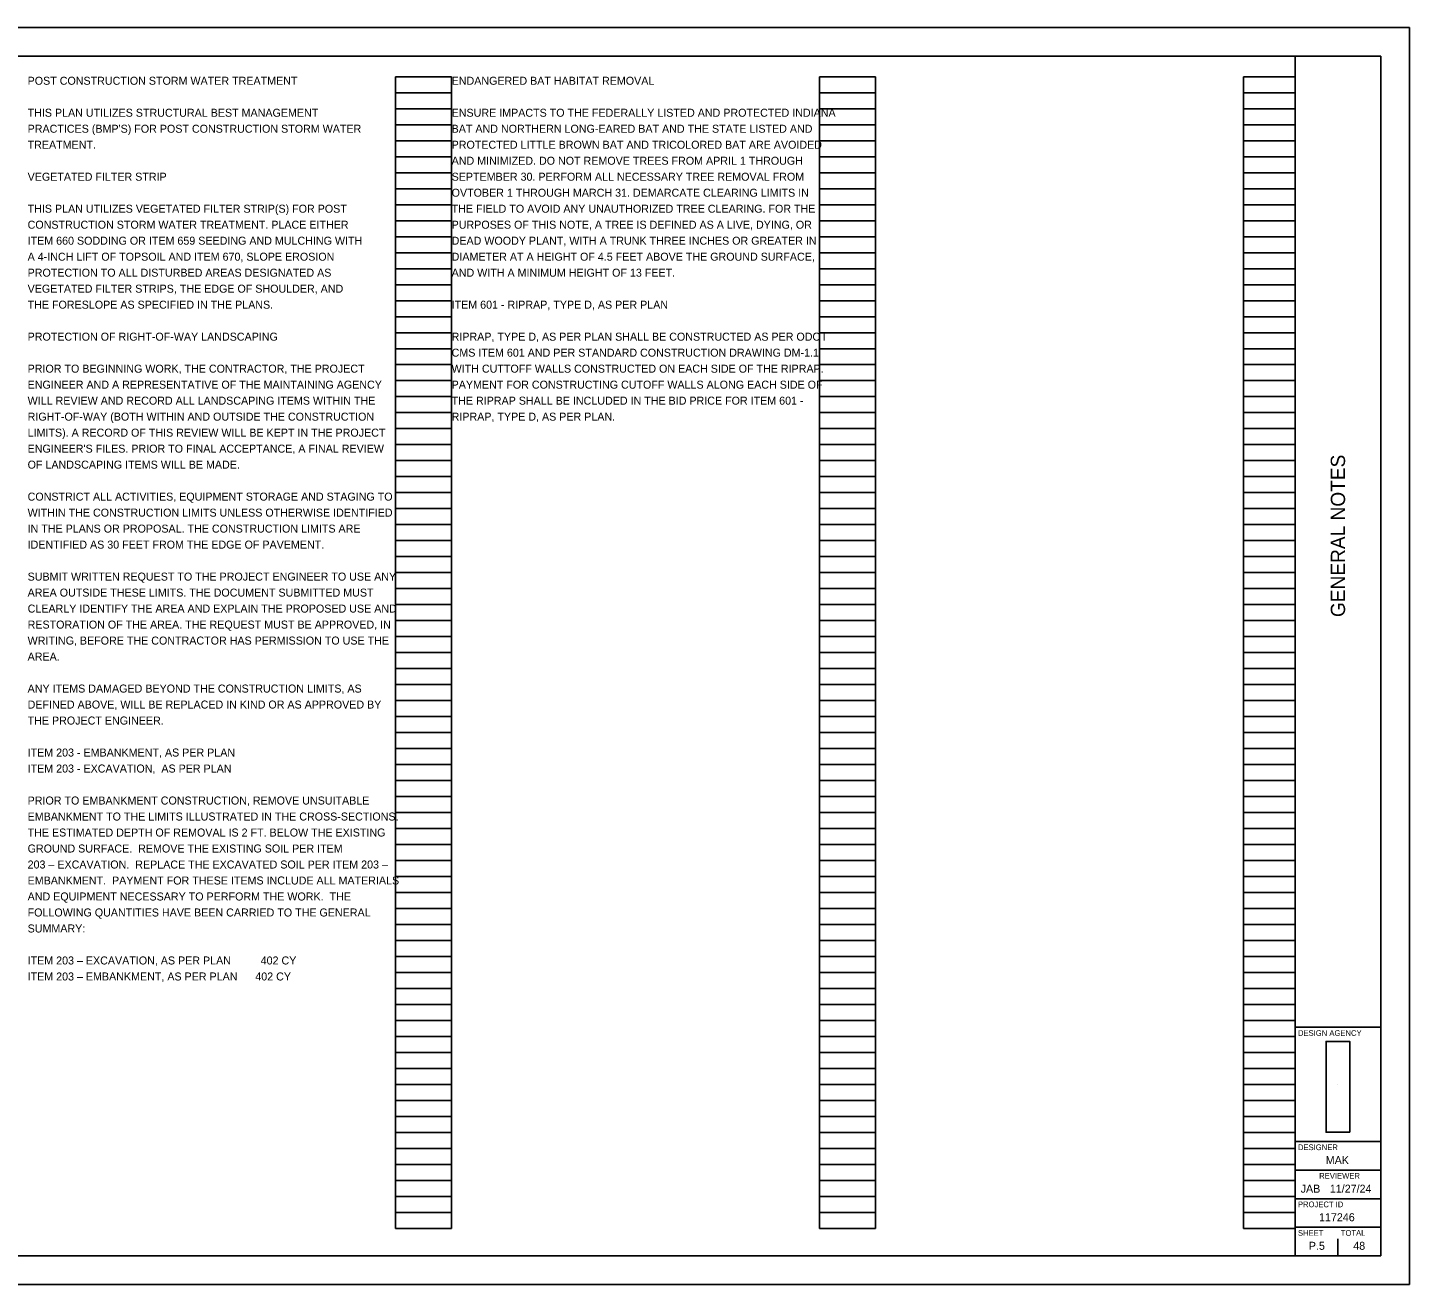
# Model space of a CAD drawing. Extents: x -14.4 to 34, y 0 to 22.
# Drawn here: x 9.82 to 34, y 0 to 22 of the extents above; entities that cross this region are included whole.
import ezdxf

# ---------------------------------------------------------------- set-up
doc = ezdxf.new("R2010")
doc.units = 0
for name, color, linetype in [('SH_Border', 7, 'Continuous'), ('SH_Cut_Line', 7, 'Continuous'), ('SH_Data', 7, 'Continuous'), ('SH_Text', 7, 'Continuous')]:
    doc.layers.add(name, color=color, linetype=linetype)

msp = doc.modelspace()

# ---------------------------------------------------------------- linework, layer by layer
at = {"layer": 'SH_Border'}
for p, q in [((32, 0.5), (32, 21.5)), ((32, 4.5), (33.5, 4.5)), ((32, 2.5), (33.5, 2.5)), ((32, 2), (33.5, 2)), ((32, 1.5), (33.5, 1.5)), ((32, 1), (33.5, 1))]:
    msp.add_line(p, q, dxfattribs=at)
msp.add_lwpolyline([(1.5, 21.5), (33.5, 21.5), (33.5, 0.5), (1.5, 0.5)], close=True, dxfattribs=at)
at = {"layer": 'SH_Cut_Line'}
msp.add_lwpolyline([(0, 0), (34, 0), (34, 22), (0, 22)], close=True, dxfattribs=at)
at = {"layer": 'SH_Data'}
for p, q in [((16.26, 0.98), (16.26, 21.14)), ((16.26, 21.14), (17.24, 21.14)), ((17.24, 0.98), (17.24, 21.14)), ((23.68, 0.98), (23.68, 21.14)), ((23.68, 21.14), (24.66, 21.14)), ((24.66, 0.98), (24.66, 21.14)), ((31.1, 0.98), (31.1, 21.14)), ((31.1, 21.14), (32, 21.14)), ((32, 0.98), (32, 21.14)), ((16.26, 20.86), (17.24, 20.86)), ((23.68, 20.86), (24.66, 20.86)), ((31.1, 20.86), (32, 20.86)), ((16.26, 20.58), (17.24, 20.58)), ((23.68, 20.58), (24.66, 20.58)), ((31.1, 20.58), (32, 20.58)), ((16.26, 20.3), (17.24, 20.3)), ((23.68, 20.3), (24.66, 20.3)), ((31.1, 20.3), (32, 20.3)), ((16.26, 20.02), (17.24, 20.02)), ((23.68, 20.02), (24.66, 20.02)), ((31.1, 20.02), (32, 20.02)), ((16.26, 19.74), (17.24, 19.74)), ((23.68, 19.74), (24.66, 19.74)), ((31.1, 19.74), (32, 19.74)), ((16.26, 19.46), (17.24, 19.46)), ((23.68, 19.46), (24.66, 19.46)), ((31.1, 19.46), (32, 19.46)), ((16.26, 19.18), (17.24, 19.18)), ((23.68, 19.18), (24.66, 19.18)), ((31.1, 19.18), (32, 19.18)), ((16.26, 18.9), (17.24, 18.9)), ((23.68, 18.9), (24.66, 18.9)), ((31.1, 18.9), (32, 18.9)), ((16.26, 18.62), (17.24, 18.62)), ((23.68, 18.62), (24.66, 18.62)), ((31.1, 18.62), (32, 18.62)), ((16.26, 18.34), (17.24, 18.34)), ((23.68, 18.34), (24.66, 18.34)), ((31.1, 18.34), (32, 18.34)), ((16.26, 18.06), (17.24, 18.06)), ((23.68, 18.06), (24.66, 18.06)), ((31.1, 18.06), (32, 18.06)), ((16.26, 17.78), (17.24, 17.78)), ((23.68, 17.78), (24.66, 17.78)), ((31.1, 17.78), (32, 17.78)), ((16.26, 17.5), (17.24, 17.5)), ((23.68, 17.5), (24.66, 17.5)), ((31.1, 17.5), (32, 17.5)), ((16.26, 17.22), (17.24, 17.22)), ((23.68, 17.22), (24.66, 17.22)), ((31.1, 17.22), (32, 17.22)), ((16.26, 16.94), (17.24, 16.94)), ((23.68, 16.94), (24.66, 16.94)), ((31.1, 16.94), (32, 16.94)), ((16.26, 16.66), (17.24, 16.66)), ((23.68, 16.66), (24.66, 16.66)), ((31.1, 16.66), (32, 16.66)), ((16.26, 16.38), (17.24, 16.38)), ((23.68, 16.38), (24.66, 16.38)), ((31.1, 16.38), (32, 16.38)), ((16.26, 16.1), (17.24, 16.1)), ((23.68, 16.1), (24.66, 16.1)), ((31.1, 16.1), (32, 16.1)), ((16.26, 15.82), (17.24, 15.82)), ((23.68, 15.82), (24.66, 15.82)), ((31.1, 15.82), (32, 15.82)), ((16.26, 15.54), (17.24, 15.54)), ((23.68, 15.54), (24.66, 15.54)), ((31.1, 15.54), (32, 15.54)), ((16.26, 15.26), (17.24, 15.26)), ((23.68, 15.26), (24.66, 15.26)), ((31.1, 15.26), (32, 15.26)), ((16.26, 14.98), (17.24, 14.98)), ((23.68, 14.98), (24.66, 14.98)), ((31.1, 14.98), (32, 14.98)), ((16.26, 14.7), (17.24, 14.7)), ((23.68, 14.7), (24.66, 14.7)), ((31.1, 14.7), (32, 14.7)), ((16.26, 14.42), (17.24, 14.42)), ((23.68, 14.42), (24.66, 14.42)), ((31.1, 14.42), (32, 14.42)), ((16.26, 14.14), (17.24, 14.14)), ((23.68, 14.14), (24.66, 14.14)), ((31.1, 14.14), (32, 14.14)), ((16.26, 13.86), (17.24, 13.86)), ((23.68, 13.86), (24.66, 13.86)), ((31.1, 13.86), (32, 13.86)), ((16.26, 13.58), (17.24, 13.58)), ((23.68, 13.58), (24.66, 13.58)), ((31.1, 13.58), (32, 13.58)), ((16.26, 13.3), (17.24, 13.3)), ((23.68, 13.3), (24.66, 13.3)), ((31.1, 13.3), (32, 13.3)), ((16.26, 13.02), (17.24, 13.02)), ((23.68, 13.02), (24.66, 13.02)), ((31.1, 13.02), (32, 13.02)), ((16.26, 12.74), (17.24, 12.74)), ((23.68, 12.74), (24.66, 12.74)), ((31.1, 12.74), (32, 12.74)), ((16.26, 12.46), (17.24, 12.46)), ((23.68, 12.46), (24.66, 12.46)), ((31.1, 12.46), (32, 12.46)), ((16.26, 12.18), (17.24, 12.18)), ((23.68, 12.18), (24.66, 12.18)), ((31.1, 12.18), (32, 12.18)), ((16.26, 11.9), (17.24, 11.9)), ((23.68, 11.9), (24.66, 11.9)), ((31.1, 11.9), (32, 11.9)), ((16.26, 11.62), (17.24, 11.62)), ((23.68, 11.62), (24.66, 11.62)), ((31.1, 11.62), (32, 11.62)), ((16.26, 11.34), (17.24, 11.34)), ((23.68, 11.34), (24.66, 11.34)), ((31.1, 11.34), (32, 11.34)), ((16.26, 11.06), (17.24, 11.06)), ((23.68, 11.06), (24.66, 11.06)), ((31.1, 11.06), (32, 11.06)), ((16.26, 10.78), (17.24, 10.78)), ((23.68, 10.78), (24.66, 10.78)), ((31.1, 10.78), (32, 10.78)), ((16.26, 10.5), (17.24, 10.5)), ((23.68, 10.5), (24.66, 10.5)), ((31.1, 10.5), (32, 10.5)), ((16.26, 10.22), (17.24, 10.22)), ((23.68, 10.22), (24.66, 10.22)), ((31.1, 10.22), (32, 10.22)), ((16.26, 9.94), (17.24, 9.94)), ((23.68, 9.94), (24.66, 9.94)), ((31.1, 9.94), (32, 9.94)), ((16.26, 9.66), (17.24, 9.66)), ((23.68, 9.66), (24.66, 9.66)), ((31.1, 9.66), (32, 9.66)), ((16.26, 9.38), (17.24, 9.38)), ((23.68, 9.38), (24.66, 9.38)), ((31.1, 9.38), (32, 9.38)), ((16.26, 9.1), (17.24, 9.1)), ((23.68, 9.1), (24.66, 9.1)), ((31.1, 9.1), (32, 9.1)), ((16.26, 8.82), (17.24, 8.82)), ((23.68, 8.82), (24.66, 8.82)), ((31.1, 8.82), (32, 8.82)), ((16.26, 8.54), (17.24, 8.54)), ((23.68, 8.54), (24.66, 8.54)), ((31.1, 8.54), (32, 8.54)), ((16.26, 8.26), (17.24, 8.26)), ((23.68, 8.26), (24.66, 8.26)), ((31.1, 8.26), (32, 8.26)), ((16.26, 7.98), (17.24, 7.98)), ((23.68, 7.98), (24.66, 7.98)), ((31.1, 7.98), (32, 7.98)), ((16.26, 7.7), (17.24, 7.7)), ((23.68, 7.7), (24.66, 7.7)), ((31.1, 7.7), (32, 7.7)), ((16.26, 7.42), (17.24, 7.42)), ((23.68, 7.42), (24.66, 7.42)), ((31.1, 7.42), (32, 7.42)), ((16.26, 7.14), (17.24, 7.14)), ((23.68, 7.14), (24.66, 7.14)), ((31.1, 7.14), (32, 7.14)), ((16.26, 6.86), (17.24, 6.86)), ((23.68, 6.86), (24.66, 6.86)), ((31.1, 6.86), (32, 6.86)), ((16.26, 6.58), (17.24, 6.58)), ((23.68, 6.58), (24.66, 6.58)), ((31.1, 6.58), (32, 6.58)), ((16.26, 6.3), (17.24, 6.3)), ((23.68, 6.3), (24.66, 6.3)), ((31.1, 6.3), (32, 6.3)), ((16.26, 6.02), (17.24, 6.02)), ((23.68, 6.02), (24.66, 6.02)), ((31.1, 6.02), (32, 6.02)), ((16.26, 5.74), (17.24, 5.74)), ((23.68, 5.74), (24.66, 5.74)), ((31.1, 5.74), (32, 5.74)), ((16.26, 5.46), (17.24, 5.46)), ((23.68, 5.46), (24.66, 5.46)), ((31.1, 5.46), (32, 5.46)), ((16.26, 5.18), (17.24, 5.18)), ((23.68, 5.18), (24.66, 5.18)), ((31.1, 5.18), (32, 5.18)), ((16.26, 4.9), (17.24, 4.9)), ((23.68, 4.9), (24.66, 4.9)), ((31.1, 4.9), (32, 4.9)), ((16.26, 4.62), (17.24, 4.62)), ((23.68, 4.62), (24.66, 4.62)), ((31.1, 4.62), (32, 4.62)), ((16.26, 4.34), (17.24, 4.34)), ((23.68, 4.34), (24.66, 4.34)), ((31.1, 4.34), (32, 4.34)), ((16.26, 4.06), (17.24, 4.06)), ((23.68, 4.06), (24.66, 4.06)), ((31.1, 4.06), (32, 4.06)), ((16.26, 3.78), (17.24, 3.78)), ((23.68, 3.78), (24.66, 3.78)), ((31.1, 3.78), (32, 3.78)), ((16.26, 3.5), (17.24, 3.5)), ((23.68, 3.5), (24.66, 3.5)), ((31.1, 3.5), (32, 3.5)), ((32.75, 3.5), (32.75, 3.5)), ((16.26, 3.22), (17.24, 3.22)), ((23.68, 3.22), (24.66, 3.22)), ((31.1, 3.22), (32, 3.22)), ((16.26, 2.94), (17.24, 2.94)), ((23.68, 2.94), (24.66, 2.94)), ((31.1, 2.94), (32, 2.94)), ((16.26, 2.66), (17.24, 2.66)), ((23.68, 2.66), (24.66, 2.66)), ((31.1, 2.66), (32, 2.66)), ((16.26, 2.38), (17.24, 2.38)), ((23.68, 2.38), (24.66, 2.38)), ((31.1, 2.38), (32, 2.38)), ((16.26, 2.1), (17.24, 2.1)), ((23.68, 2.1), (24.66, 2.1)), ((31.1, 2.1), (32, 2.1)), ((16.26, 1.82), (17.24, 1.82)), ((23.68, 1.82), (24.66, 1.82)), ((31.1, 1.82), (32, 1.82)), ((16.26, 1.54), (17.24, 1.54)), ((23.68, 1.54), (24.66, 1.54)), ((31.1, 1.54), (32, 1.54)), ((16.26, 1.26), (17.24, 1.26)), ((23.68, 1.26), (24.66, 1.26)), ((31.1, 1.26), (32, 1.26)), ((16.26, 0.98), (17.24, 0.98)), ((23.68, 0.98), (24.66, 0.98)), ((31.1, 0.98), (32, 0.98)), ((32.75, 0.5), (32.75, 0.8)), ((32.375, 0.675), (32.375, 0.675))]:
    msp.add_line(p, q, dxfattribs=at)
at = {"layer": 'SH_Text'}
msp.add_lwpolyline([(32.956, 2.664), (32.956, 4.254), (32.544, 4.254), (32.544, 2.664)], close=True, dxfattribs=at)

# ---------------------------------------------------------------- texts
at = {"layer": 'SH_Data'}
msp.add_text('GENERAL NOTES', height=0.25, rotation=90, dxfattribs=at).set_placement((32.875, 11.682))
for s, height, p in [('DESIGN AGENCY', 0.1, (32.05, 4.35)), ('DESIGNER', 0.1, (32.05, 2.35)), ('MAK', 0.14, (32.537, 2.105)), ('REVIEWER', 0.1, (32.422, 1.85)), ('JAB', 0.14, (32.098, 1.605)), ('11/27/24', 0.14, (32.608, 1.605)), ('PROJECT ID', 0.1, (32.05, 1.35)), ('117246', 0.14, (32.419, 1.105)), ('SHEET', 0.1, (32.05, 0.85)), ('P.5', 0.14, (32.241, 0.605)), ('TOTAL', 0.1, (32.8, 0.85)), ('48', 0.14, (33.018, 0.605))]:
    msp.add_text(s, height=height, dxfattribs=at).set_placement(p)
at = {"layer": 'SH_Text'}
for s, p in [('POST CONSTRUCTION STORM WATER TREATMENT', (9.82, 21)), ('ENDANGERED BAT HABITAT REMOVAL', (17.24, 21)), ('THIS PLAN UTILIZES STRUCTURAL BEST MANAGEMENT', (9.82, 20.44)), ('ENSURE IMPACTS TO THE FEDERALLY LISTED AND PROTECTED INDIANA ', (17.24, 20.44)), ("PRACTICES (BMP'S) FOR POST CONSTRUCTION STORM WATER", (9.82, 20.16)), ('BAT AND NORTHERN LONG-EARED BAT AND THE STATE LISTED AND ', (17.24, 20.16)), ('TREATMENT.', (9.82, 19.88)), ('PROTECTED LITTLE BROWN BAT AND TRICOLORED BAT ARE AVOIDED ', (17.24, 19.88)), ('AND MINIMIZED. DO NOT REMOVE TREES FROM APRIL 1 THROUGH ', (17.24, 19.6)), ('VEGETATED FILTER STRIP', (9.82, 19.32)), ('SEPTEMBER 30. PERFORM ALL NECESSARY TREE REMOVAL FROM ', (17.24, 19.32)), ('OVTOBER 1 THROUGH MARCH 31. DEMARCATE CLEARING LIMITS IN ', (17.24, 19.04)), ('THIS PLAN UTILIZES VEGETATED FILTER STRIP(S) FOR POST', (9.82, 18.76)), ('THE FIELD TO AVOID ANY UNAUTHORIZED TREE CLEARING. FOR THE ', (17.24, 18.76)), ('CONSTRUCTION STORM WATER TREATMENT. PLACE EITHER', (9.82, 18.48)), ('PURPOSES OF THIS NOTE, A TREE IS DEFINED AS A LIVE, DYING, OR ', (17.24, 18.48)), ('ITEM 660 SODDING OR ITEM 659 SEEDING AND MULCHING WITH', (9.82, 18.2)), ('DEAD WOODY PLANT, WITH A TRUNK THREE INCHES OR GREATER IN ', (17.24, 18.2)), ('A 4-INCH LIFT OF TOPSOIL AND ITEM 670, SLOPE EROSION', (9.82, 17.92)), ('DIAMETER AT A HEIGHT OF 4.5 FEET ABOVE THE GROUND SURFACE, ', (17.24, 17.92)), ('PROTECTION TO ALL DISTURBED AREAS DESIGNATED AS', (9.82, 17.64)), ('AND WITH A MINIMUM HEIGHT OF 13 FEET.', (17.24, 17.64)), ('VEGETATED FILTER STRIPS, THE EDGE OF SHOULDER, AND', (9.82, 17.36)), ('THE FORESLOPE AS SPECIFIED IN THE PLANS.', (9.82, 17.08)), ('ITEM 601 - RIPRAP, TYPE D, AS PER PLAN', (17.24, 17.08)), ('PROTECTION OF RIGHT-OF-WAY LANDSCAPING', (9.82, 16.52)), ('RIPRAP, TYPE D, AS PER PLAN SHALL BE CONSTRUCTED AS PER ODOT ', (17.24, 16.52)), ('CMS ITEM 601 AND PER STANDARD CONSTRUCTION DRAWING DM-1.1 ', (17.24, 16.24)), ('PRIOR TO BEGINNING WORK, THE CONTRACTOR, THE PROJECT', (9.82, 15.96)), ('WITH CUTTOFF WALLS CONSTRUCTED ON EACH SIDE OF THE RIPRAP. ', (17.24, 15.96)), ('ENGINEER AND A REPRESENTATIVE OF THE MAINTAINING AGENCY', (9.82, 15.68)), ('PAYMENT FOR CONSTRUCTING CUTOFF WALLS ALONG EACH SIDE OF ', (17.24, 15.68)), ('WILL REVIEW AND RECORD ALL LANDSCAPING ITEMS WITHIN THE', (9.82, 15.4)), ('THE RIPRAP SHALL BE INCLUDED IN THE BID PRICE FOR ITEM 601 - ', (17.24, 15.4)), ('RIGHT-OF-WAY (BOTH WITHIN AND OUTSIDE THE CONSTRUCTION', (9.82, 15.12)), ('RIPRAP, TYPE D, AS PER PLAN.', (17.24, 15.12)), ('LIMITS). A RECORD OF THIS REVIEW WILL BE KEPT IN THE PROJECT', (9.82, 14.84)), ("ENGINEER'S FILES. PRIOR TO FINAL ACCEPTANCE, A FINAL REVIEW", (9.82, 14.56)), ('OF LANDSCAPING ITEMS WILL BE MADE.', (9.82, 14.28)), ('CONSTRICT ALL ACTIVITIES, EQUIPMENT STORAGE AND STAGING TO', (9.82, 13.72)), ('WITHIN THE CONSTRUCTION LIMITS UNLESS OTHERWISE IDENTIFIED', (9.82, 13.44)), ('IN THE PLANS OR PROPOSAL. THE CONSTRUCTION LIMITS ARE', (9.82, 13.16)), ('IDENTIFIED AS 30 FEET FROM THE EDGE OF PAVEMENT.', (9.82, 12.88)), ('SUBMIT WRITTEN REQUEST TO THE PROJECT ENGINEER TO USE ANY', (9.82, 12.32)), ('AREA OUTSIDE THESE LIMITS. THE DOCUMENT SUBMITTED MUST', (9.82, 12.04)), ('CLEARLY IDENTIFY THE AREA AND EXPLAIN THE PROPOSED USE AND', (9.82, 11.76)), ('RESTORATION OF THE AREA. THE REQUEST MUST BE APPROVED, IN', (9.82, 11.48)), ('WRITING, BEFORE THE CONTRACTOR HAS PERMISSION TO USE THE', (9.82, 11.2)), ('AREA.', (9.82, 10.92)), ('ANY ITEMS DAMAGED BEYOND THE CONSTRUCTION LIMITS, AS', (9.82, 10.36)), ('DEFINED ABOVE, WILL BE REPLACED IN KIND OR AS APPROVED BY', (9.82, 10.08)), ('THE PROJECT ENGINEER.', (9.82, 9.8)), ('ITEM 203 - EMBANKMENT, AS PER PLAN', (9.82, 9.24)), ('ITEM 203 - EXCAVATION,  AS PER PLAN', (9.82, 8.96)), ('PRIOR TO EMBANKMENT CONSTRUCTION, REMOVE UNSUITABLE', (9.82, 8.4)), ('EMBANKMENT TO THE LIMITS ILLUSTRATED IN THE CROSS-SECTIONS.  ', (9.82, 8.12)), ('THE ESTIMATED DEPTH OF REMOVAL IS 2 FT. BELOW THE EXISTING ', (9.82, 7.84)), ('GROUND SURFACE.  REMOVE THE EXISTING SOIL PER ITEM ', (9.82, 7.56)), ('203 – EXCAVATION.  REPLACE THE EXCAVATED SOIL PER ITEM 203 – ', (9.82, 7.28)), ('EMBANKMENT.  PAYMENT FOR THESE ITEMS INCLUDE ALL MATERIALS ', (9.82, 7)), ('AND EQUIPMENT NECESSARY TO PERFORM THE WORK.  THE ', (9.82, 6.72)), ('FOLLOWING QUANTITIES HAVE BEEN CARRIED TO THE GENERAL', (9.82, 6.44)), ('SUMMARY:', (9.82, 6.16)), ('ITEM 203 – EXCAVATION, AS PER PLAN          402 CY', (9.82, 5.6)), ('ITEM 203 – EMBANKMENT, AS PER PLAN      402 CY', (9.82, 5.32))]:
    msp.add_text(s, height=0.14, dxfattribs=at).set_placement(p)

doc.saveas('drawing.dxf')
